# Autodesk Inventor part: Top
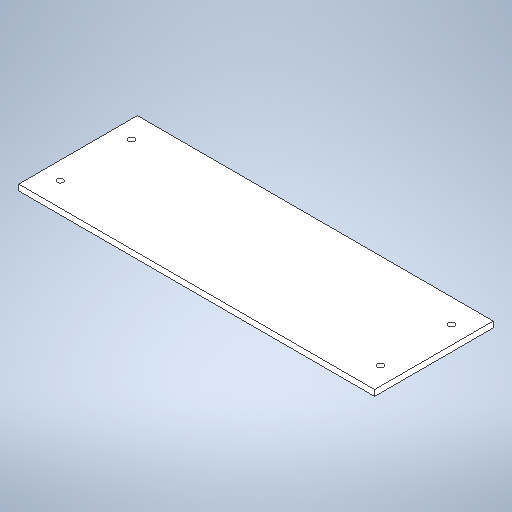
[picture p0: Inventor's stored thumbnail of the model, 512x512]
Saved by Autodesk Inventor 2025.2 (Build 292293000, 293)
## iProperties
Created: 2025-09
Part Number: Top
Material: Generic
Document SubType Name: Modeling
Designer: tyler
Density: 1 g/cm^3
Appearance: Default
Author: tyler
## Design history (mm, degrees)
sketch "Sketch1"
  geometry: L1 (190.5, 63.5)-(-190.5, 63.5); L2 (-190.5, 63.5)-(-190.5, -63.5); L3 (-190.5, -63.5)-(190.5, -63.5); L4 (190.5, -63.5)-(190.5, 63.5); L5 (190.5, 63.5)-(-190.5, -63.5); L6 (-190.5, 63.5)-(190.5, -63.5); 1 further point
  constraints: 12 end point, 2 midpoint, 2 parallel, 1 horizontal, 1 perpendicular
  dimensions: "d0" = 381 distance of L3.end L2.end; "d1" = 127 distance of L2.end L1.end
extrude "Extrusion1" new body sketch "Sketch1" distance "d2" = 6.35; taper "d3" = 0 deg
sketch "Sketch2"
  geometry: L1 (-190.5, -63.5)-(190.5, -63.5) reference; L2 (0, -63.5)-(0, -47.815); L3 (-190.5, -63.5)-(-190.5, -38.1); L4 (-190.5, 63.5)-(-190.5, -63.5) reference; L5 (-190.5, -38.1)-(-171.45, -38.1); L6 (-190.5, 63.5)-(-190.5, 38.1); L7 (-190.5, 38.1)-(-171.45, 38.1); C1 r 3.175 at (-171.45, -38.1); C2 r 3.175 at (-171.45, 38.1); C3 r 3.175 at (171.45, -38.1); C4 r 3.175 at (171.45, 38.1); 1 further point
  constraints: 10 end point, 4 centre point, 2 coincident, 2 point on line, 2 symmetric about line, 1 horizontal, 1 midpoint, 1 perpendicular, 1 vertical, 2 other
  dimensions: "d4" = 25.4 distance of L1.start L3.end; "d5" = 19.05 distance of L3.end L5.end; "d6" = 25.4 distance of L4.start L6.end; "d7" = 19.05 distance of L6.end L7.end; "d8" = 6.35 diameter of C1; "d9" = 6.35 diameter of C2
extrude "Extrusion2" cut sketch "Sketch2" distance "d10" = 6.35; taper "d11" = 0 deg
body "Solid1"
